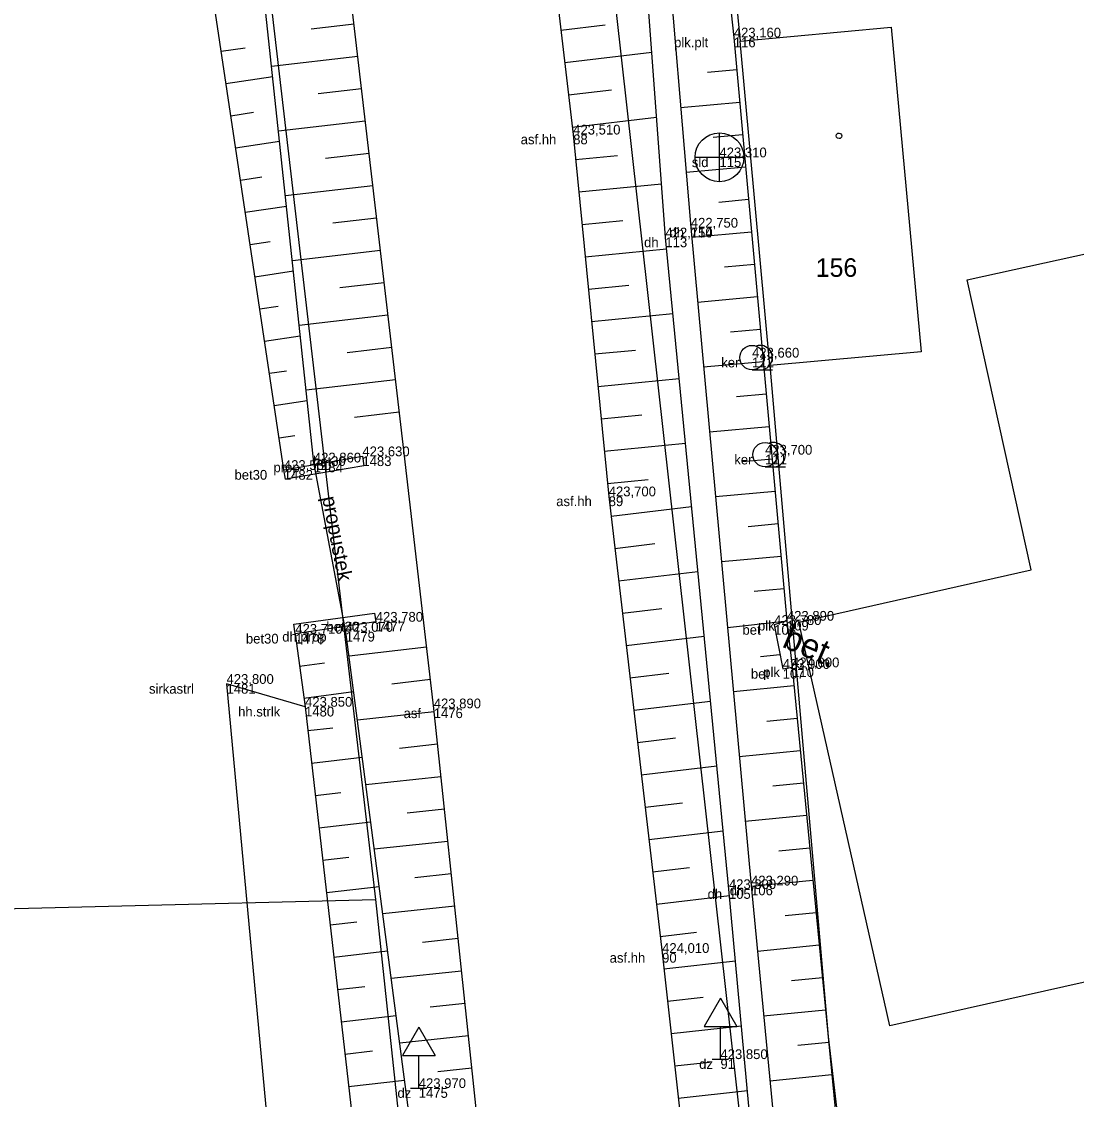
# Model space of a CAD drawing. Extents: x -747792 to -745414, y -1093712 to -1091463.
# Drawn here: x -746652 to -746619.62, y -1092747.87 to -1092714.77 of the extents above; entities that cross this region are included whole.
import ezdxf

# ---------------------------------------------------------------- set-up
doc = ezdxf.new("R2010")
doc.units = 0
for name, color, linetype in [('Hladina', 7, 'Continuous'), ('Koleje_dopravní prvky', 7, 'Continuous'), ('Nezařazené objekty', 7, 'Continuous'), ('Nivelační značky_hrany', 7, 'Continuous'), ('Názvy obcí_ulic', 7, 'Continuous'), ('Ploty_opěrné zdi', 7, 'Continuous'), ('Pracovní_bod JDTM STC_VC - výška', 7, 'Continuous'), ('Pracovní_bod PPBP', 7, 'Continuous'), ('Pracovní_bod PPBP - číslo', 7, 'Continuous'), ('Pracovní_bod ZPBP', 7, 'Continuous'), ('Pracovní_bod ZPBP - číslo', 7, 'Continuous'), ('Rozhraní ploch', 7, 'Continuous'), ('Stromy_porost', 7, 'Continuous'), ('Výškopis', 7, 'Continuous'), ('Čísla popisná_parcelní', 7, 'Continuous')]:
    doc.layers.add(name, color=color, linetype=linetype)

msp = doc.modelspace()

# ---------------------------------------------------------------- linework, layer by layer
at = {"layer": 'Hladina'}
for p, q in [((-746630.14, -1092715.26), (-746630.14, -1092715.26)), ((-746635.07, -1092718.24), (-746635.07, -1092718.24)), ((-746630.58, -1092718.94), (-746630.58, -1092718.94)), ((-746631.46, -1092721.1), (-746631.46, -1092721.1)), ((-746632.24, -1092721.4), (-746632.24, -1092721.4)), ((-746629.58, -1092725.09), (-746629.58, -1092725.09)), ((-746641.54, -1092728.12), (-746641.54, -1092728.12)), ((-746629.18, -1092728.07), (-746629.18, -1092728.07)), ((-746643.95, -1092728.54), (-746643.95, -1092728.54)), ((-746643.03, -1092728.31), (-746643.03, -1092728.31)), ((-746633.98, -1092729.35), (-746633.98, -1092729.35)), ((-746641.13, -1092733.2), (-746641.13, -1092733.2)), ((-746628.51, -1092733.17), (-746628.51, -1092733.17)), ((-746642.05, -1092733.51), (-746642.05, -1092733.51)), ((-746628.9, -1092733.3), (-746628.9, -1092733.3)), ((-746643.6, -1092733.57), (-746643.6, -1092733.57)), ((-746628.64, -1092734.65), (-746628.64, -1092734.65)), ((-746628.35, -1092734.6), (-746628.35, -1092734.6)), ((-746645.71, -1092735.11), (-746645.71, -1092735.11)), ((-746643.3, -1092735.81), (-746643.3, -1092735.81)), ((-746639.35, -1092735.86), (-746639.35, -1092735.86)), ((-746630.29, -1092741.41), (-746630.29, -1092741.41)), ((-746629.61, -1092741.3), (-746629.61, -1092741.3)), ((-746632.34, -1092743.37), (-746632.34, -1092743.37)), ((-746630.55, -1092746.63), (-746630.55, -1092746.63)), ((-746639.81, -1092747.52), (-746639.81, -1092747.52))]:
    msp.add_line(p, q, dxfattribs=at)
at = {"layer": 'Nezařazené objekty'}
for points in [[(-746631.05, -1092667.87), (-746635.97, -1092668.97), (-746634.11, -1092682.81), (-746632.69, -1092695.31), (-746631.46, -1092703.01), (-746630.14, -1092715.26)], [(-746630.14, -1092715.26), (-746628.51, -1092733.17), (-746628.35, -1092734.6), (-746626.39, -1092754.68)]]:
    msp.add_lwpolyline(points, dxfattribs=at)
at = {"layer": 'Nivelační značky_hrany'}
for points in [[(-746640.293, -1092727.76), (-746642.73, -1092706.84), (-746645.07, -1092684.23), (-746647.45, -1092662.17), (-746649.23, -1092645.87), (-746651.64, -1092623.4), (-746654, -1092600.5), (-746655.65, -1092585.38), (-746656.67, -1092576.42), (-746659.12, -1092561.65), (-746661.88, -1092550.86), (-746667.11, -1092535.97), (-746671.93, -1092526), (-746677.329, -1092516.06)], [(-746638.62, -1092670.38), (-746639.61, -1092674.4), (-746639.44, -1092678.91), (-746638.64, -1092688.08), (-746636.95, -1092702.22), (-746635.07, -1092718.24), (-746633.98, -1092729.35), (-746632.34, -1092743.37), (-746630.46, -1092760.33), (-746628.78, -1092773.02)], [(-746639.676, -1092733.059), (-746640.293, -1092727.763)], [(-746643.95, -1092728.54), (-746641.54, -1092728.12), (-746641.491, -1092728.416), (-746643.897, -1092728.82), (-746643.95, -1092728.54)], [(-746641.13, -1092733.2), (-746643.6, -1092733.57), (-746643.64, -1092733.273), (-746641.172, -1092732.94), (-746641.13, -1092733.2)], [(-746631.6, -1092801.51), (-746633.92, -1092784.4), (-746635.62, -1092771.08), (-746639.35, -1092735.86), (-746639.676, -1092733.06)], [(-746628.51, -1092733.17), (-746628.9, -1092733.3), (-746628.64, -1092734.65), (-746628.35, -1092734.6)]]:
    msp.add_lwpolyline(points, dxfattribs=at)
at = {"layer": 'Názvy obcí_ulic'}
for p, q in [((-746630.55, -1092744.764), (-746631.05, -1092745.63)), ((-746630.55, -1092744.764), (-746630.05, -1092745.63)), ((-746639.81, -1092745.654), (-746640.31, -1092746.52)), ((-746639.81, -1092745.654), (-746639.31, -1092746.52)), ((-746631.05, -1092745.63), (-746630.05, -1092745.63)), ((-746630.55, -1092746.63), (-746630.55, -1092745.63)), ((-746640.31, -1092746.52), (-746639.31, -1092746.52)), ((-746639.81, -1092747.52), (-746639.81, -1092746.52)), ((-746630.8, -1092746.63), (-746630.3, -1092746.63)), ((-746640.06, -1092747.52), (-746639.56, -1092747.52))]:
    msp.add_line(p, q, dxfattribs=at)
at = {"layer": 'Ploty_opěrné zdi'}
msp.add_lwpolyline([(-746626.91, -1092718.195), (-746626.86, -1092718.205), (-746626.835, -1092718.25), (-746626.825, -1092718.28), (-746626.835, -1092718.325), (-746626.875, -1092718.36), (-746626.91, -1092718.365), (-746626.955, -1092718.35), (-746626.985, -1092718.32), (-746626.995, -1092718.28), (-746626.985, -1092718.235), (-746626.945, -1092718.2)], close=True, dxfattribs=at)
at = {"layer": 'Pracovní_bod JDTM STC_VC - výška'}
msp.add_lwpolyline([(-746643.3, -1092735.81), (-746645.71, -1092735.11), (-746642.51, -1092769.58), (-746639.22, -1092771.37)], dxfattribs=at)
at = {"layer": 'Pracovní_bod PPBP'}
for points in [[(-746643.03, -1092728.31), (-746645.35, -1092706.55), (-746647.64, -1092685.53), (-746650.22, -1092662.21), (-746652.01, -1092645.97), (-746654.41, -1092623.21), (-746657.16, -1092600.72), (-746657.52, -1092586.28), (-746659.03, -1092575.98), (-746661.36, -1092561.58), (-746663.99, -1092551.17), (-746668.72, -1092536.82), (-746673.6, -1092526.76), (-746679.03, -1092516.89)], [(-746643.95, -1092728.54), (-746647.21, -1092706.78), (-746649.33, -1092686.28), (-746651.4, -1092662.02)], [(-746627.38, -1092772.91), (-746628.52, -1092760.62), (-746630.29, -1092741.41), (-746632.24, -1092721.4), (-746632.95, -1092711.71), (-746633.31, -1092703.22), (-746634.38, -1092695.54), (-746635.8, -1092684.01), (-746637.93, -1092670.61)], [(-746637.24, -1092670.41), (-746635.08, -1092683.82), (-746633.69, -1092695.33), (-746632.62, -1092703.25), (-746632.27, -1092711.5), (-746631.46, -1092721.1), (-746629.61, -1092741.3), (-746627.76, -1092760.57), (-746626.45, -1092772.93)], [(-746641.797, -1092714.848), (-746643.115, -1092715.001)], [(-746635.446, -1092715.033), (-746634.088, -1092714.874)], [(-746645.876, -1092715.683), (-746645.138, -1092715.573)], [(-746641.682, -1092715.841), (-746644.327, -1092716.149)], [(-746635.33, -1092716.026), (-746632.657, -1092715.713)], [(-746630.049, -1092716.256), (-746630.952, -1092716.338)], [(-746645.728, -1092716.672), (-746644.294, -1092716.458)], [(-746641.566, -1092716.834), (-746642.893, -1092716.989)], [(-746635.213, -1092717.02), (-746633.898, -1092716.865)], [(-746629.959, -1092717.252), (-746631.771, -1092717.417)], [(-746645.58, -1092717.661), (-746644.884, -1092717.557)], [(-746641.45, -1092717.828), (-746644.115, -1092718.138)], [(-746635.097, -1092718.013), (-746632.51, -1092717.709)], [(-746629.868, -1092718.248), (-746630.777, -1092718.33)], [(-746645.432, -1092718.65), (-746644.081, -1092718.448)], [(-746641.335, -1092718.821), (-746642.672, -1092718.977)], [(-746634.995, -1092719.008), (-746633.714, -1092718.882)], [(-746629.777, -1092719.244), (-746631.603, -1092719.41)], [(-746645.283, -1092719.639), (-746644.629, -1092719.541)], [(-746641.219, -1092719.814), (-746643.902, -1092720.127)], [(-746634.897, -1092720.003), (-746632.361, -1092719.754)], [(-746629.687, -1092720.239), (-746630.603, -1092720.323)], [(-746645.135, -1092720.628), (-746643.869, -1092720.439)], [(-746641.103, -1092720.807), (-746642.45, -1092720.964)], [(-746634.799, -1092720.998), (-746633.543, -1092720.875)], [(-746629.596, -1092721.235), (-746631.432, -1092721.402)], [(-746644.987, -1092721.617), (-746644.375, -1092721.526)], [(-746640.988, -1092721.801), (-746643.69, -1092722.115)], [(-746634.702, -1092721.993), (-746632.206, -1092721.748)], [(-746629.506, -1092722.231), (-746630.423, -1092722.315)], [(-746644.839, -1092722.606), (-746643.657, -1092722.429)], [(-746640.872, -1092722.794), (-746642.228, -1092722.952)], [(-746634.604, -1092722.988), (-746633.357, -1092722.866)], [(-746629.415, -1092723.227), (-746631.25, -1092723.394)], [(-746644.691, -1092723.595), (-746644.121, -1092723.51)], [(-746640.756, -1092723.787), (-746643.478, -1092724.104)], [(-746634.506, -1092723.984), (-746632.012, -1092723.739)], [(-746629.324, -1092724.223), (-746630.241, -1092724.306)], [(-746644.543, -1092724.584), (-746643.445, -1092724.42)], [(-746640.64, -1092724.781), (-746642.006, -1092724.94)], [(-746634.409, -1092724.979), (-746633.162, -1092724.857)], [(-746629.234, -1092725.219), (-746631.067, -1092725.386)], [(-746644.394, -1092725.573), (-746643.867, -1092725.494)], [(-746640.525, -1092725.774), (-746643.266, -1092726.093)], [(-746634.311, -1092725.974), (-746631.818, -1092725.73)], [(-746629.143, -1092726.215), (-746630.06, -1092726.298)], [(-746644.246, -1092726.562), (-746643.233, -1092726.41)], [(-746640.409, -1092726.767), (-746641.785, -1092726.927)], [(-746634.214, -1092726.969), (-746632.967, -1092726.847)], [(-746629.052, -1092727.211), (-746630.885, -1092727.377)], [(-746644.098, -1092727.551), (-746643.612, -1092727.478)], [(-746634.116, -1092727.965), (-746631.624, -1092727.72)], [(-746628.962, -1092728.206), (-746629.878, -1092728.29)], [(-746634.018, -1092728.96), (-746632.773, -1092728.838)], [(-746628.871, -1092729.202), (-746630.703, -1092729.369)], [(-746633.909, -1092729.954), (-746631.435, -1092729.664)], [(-746628.78, -1092730.198), (-746629.696, -1092730.282)], [(-746633.793, -1092730.947), (-746632.565, -1092730.803)], [(-746628.69, -1092731.194), (-746630.52, -1092731.361)], [(-746633.677, -1092731.94), (-746631.241, -1092731.655)], [(-746628.599, -1092732.19), (-746629.514, -1092732.273)], [(-746633.561, -1092732.934), (-746632.352, -1092732.792)], [(-746628.595, -1092733.196), (-746630.334, -1092733.39)], [(-746633.23, -1092801.81), (-746633.34, -1092799.18), (-746635.14, -1092785.2), (-746636.97, -1092772.24), (-746642.05, -1092733.51)], [(-746643.6, -1092733.57), (-746643.3, -1092735.81), (-746639.22, -1092771.37), (-746638.71, -1092772.84), (-746637.46, -1092782.53), (-746636.71, -1092786.88), (-746634.79, -1092797.88), (-746635.62, -1092802.2)], [(-746633.445, -1092733.927), (-746631.047, -1092733.646)], [(-746639.568, -1092733.984), (-746641.951, -1092734.262)], [(-746643.467, -1092734.561), (-746642.703, -1092734.459)], [(-746628.723, -1092734.216), (-746629.32, -1092734.283)], [(-746633.328, -1092734.92), (-746632.139, -1092734.781)], [(-746639.453, -1092734.978), (-746640.637, -1092735.115)], [(-746628.294, -1092735.174), (-746630.154, -1092735.356)], [(-746643.335, -1092735.552), (-746641.809, -1092735.348)], [(-746633.212, -1092735.913), (-746630.853, -1092735.637)], [(-746639.338, -1092735.971), (-746641.694, -1092736.22)], [(-746628.197, -1092736.17), (-746629.13, -1092736.261)], [(-746643.216, -1092736.545), (-746642.445, -1092736.457)], [(-746633.096, -1092736.906), (-746631.926, -1092736.77)], [(-746639.233, -1092736.965), (-746640.399, -1092737.089)], [(-746628.1, -1092737.165), (-746629.972, -1092737.348)], [(-746643.102, -1092737.539), (-746641.545, -1092737.36)], [(-746632.98, -1092737.9), (-746630.659, -1092737.628)], [(-746639.128, -1092737.96), (-746641.434, -1092738.204)], [(-746628.002, -1092738.16), (-746628.942, -1092738.252)], [(-746642.988, -1092738.532), (-746642.201, -1092738.442)], [(-746632.864, -1092738.893), (-746631.713, -1092738.758)], [(-746639.022, -1092738.954), (-746640.163, -1092739.075)], [(-746627.905, -1092739.155), (-746629.79, -1092739.339)], [(-746642.874, -1092739.526), (-746641.285, -1092739.343)], [(-746632.748, -1092739.886), (-746630.465, -1092739.619)], [(-746638.917, -1092739.949), (-746641.174, -1092740.188)], [(-746627.808, -1092740.151), (-746628.753, -1092740.243)], [(-746642.76, -1092740.519), (-746641.957, -1092740.427)], [(-746632.631, -1092740.879), (-746631.499, -1092740.747)], [(-746638.812, -1092740.943), (-746639.928, -1092741.061)], [(-746627.711, -1092741.146), (-746629.607, -1092741.331)], [(-746642.646, -1092741.513), (-746641.025, -1092741.327)], [(-746632.515, -1092741.873), (-746630.272, -1092741.61)], [(-746638.706, -1092741.938), (-746640.914, -1092742.171)], [(-746627.614, -1092742.141), (-746628.563, -1092742.234)], [(-746642.532, -1092742.506), (-746641.713, -1092742.412)], [(-746632.399, -1092742.866), (-746631.289, -1092742.736)], [(-746638.601, -1092742.932), (-746639.692, -1092743.048)], [(-746627.517, -1092743.136), (-746629.416, -1092743.322)], [(-746642.418, -1092743.5), (-746640.765, -1092743.31)], [(-746632.286, -1092743.859), (-746630.087, -1092743.616)], [(-746638.496, -1092743.926), (-746640.654, -1092744.155)], [(-746627.42, -1092744.132), (-746628.37, -1092744.225)], [(-746642.304, -1092744.493), (-746641.469, -1092744.397)], [(-746632.176, -1092744.853), (-746631.085, -1092744.732)], [(-746638.39, -1092744.921), (-746639.457, -1092745.034)], [(-746627.322, -1092745.127), (-746629.225, -1092745.313)], [(-746642.19, -1092745.487), (-746640.504, -1092745.293)], [(-746632.065, -1092745.847), (-746629.903, -1092745.608)], [(-746638.285, -1092745.915), (-746640.394, -1092746.139)], [(-746642.076, -1092746.48), (-746641.225, -1092746.382)], [(-746627.225, -1092746.122), (-746628.177, -1092746.215)], [(-746631.955, -1092746.841), (-746630.883, -1092746.722)], [(-746638.18, -1092746.91), (-746639.222, -1092747.02)], [(-746641.962, -1092747.473), (-746640.244, -1092747.276)], [(-746627.128, -1092747.118), (-746629.034, -1092747.304)], [(-746631.845, -1092747.835), (-746629.72, -1092747.599)]]:
    msp.add_lwpolyline(points, dxfattribs=at)
at = {"layer": 'Pracovní_bod PPBP - číslo'}
for p, q in [((-746629.58, -1092725.465), (-746628.955, -1092725.465)), ((-746629.18, -1092728.445), (-746628.555, -1092728.445))]:
    msp.add_line(p, q, dxfattribs=at)
for centre in [(-746629.58, -1092725.09), (-746629.18, -1092728.07)]:
    msp.add_circle(centre, 0.375, dxfattribs=at)
for centre in [(-746629.33, -1092725.09), (-746628.93, -1092728.07)]:
    msp.add_arc(centre, 0.375, 249.4944, 109.0474, dxfattribs=at)
at = {"layer": 'Pracovní_bod ZPBP'}
msp.add_lwpolyline([(-746642.05, -1092733.51), (-746643.03, -1092728.31)], dxfattribs=at)
at = {"layer": 'Stromy_porost'}
for points in [[(-746635.22, -1092661.8), (-746629.94, -1092715.37)], [(-746635.99, -1092694.45), (-746628.46, -1092761.78)], [(-746645.62, -1092703.3), (-746641.14, -1092741.73)], [(-746629.94, -1092715.37), (-746625.31, -1092714.94)], [(-746625.31, -1092714.94), (-746624.39, -1092724.91)], [(-746629.03, -1092725.33), (-746629.94, -1092715.37)], [(-746622.98, -1092722.7), (-746607.9, -1092719.39)], [(-746621.01, -1092731.61), (-746622.98, -1092722.7)], [(-746624.39, -1092724.91), (-746629.03, -1092725.33)], [(-746629.03, -1092725.33), (-746627.24, -1092745.94)], [(-746628.14, -1092733.21), (-746621.01, -1092731.61)], [(-746625.35, -1092745.61), (-746628.14, -1092733.21)], [(-746682.12, -1092742.75), (-746641.14, -1092741.73)], [(-746641.14, -1092741.73), (-746637.96, -1092771.64)], [(-746610.42, -1092742.26), (-746625.35, -1092745.61)], [(-746627.24, -1092745.94), (-746621.8, -1092792.34)]]:
    msp.add_lwpolyline(points, dxfattribs=at)
at = {"layer": 'Čísla popisná_parcelní'}
for p, q in [((-746630.581, -1092719.688), (-746630.58, -1092718.193)), ((-746629.828, -1092718.946), (-746631.328, -1092718.941))]:
    msp.add_line(p, q, dxfattribs=at)
msp.add_circle((-746630.58, -1092718.94), 0.75, dxfattribs=at)

# ---------------------------------------------------------------- texts
at = {"layer": 'Koleje_dopravní prvky'}
msp.add_text('156', height=0.57, dxfattribs=at).set_placement((-746627.624, -1092722.61))
at = {"layer": 'Pracovní_bod ZPBP - číslo'}
for s, height, rotation, p in [('propustek', 0.45, 280.8807, (-746642.779, -1092729.387)), ('bet.', 0.75, 336.8014, (-746628.691, -1092733.96))]:
    msp.add_text(s, height=height, rotation=rotation, dxfattribs=at).set_placement(p)
at = {"layer": 'Rozhraní ploch'}
for s, p in [(' plk.plt', (-746632.084, -1092715.56)), ('116', (-746630.14, -1092715.56)), (' asf.hh', (-746636.792, -1092718.54)), ('88', (-746635.07, -1092718.54)), (' sld', (-746631.541, -1092719.24)), ('115', (-746630.58, -1092719.24)), (' dh', (-746632.225, -1092721.4)), ('114', (-746631.46, -1092721.4)), (' dh', (-746633.005, -1092721.7)), ('113', (-746632.24, -1092721.7)), (' ker', (-746630.636, -1092725.39)), ('112', (-746629.58, -1092725.39)), (' bet30', (-746643.167, -1092728.42)), ('1483', (-746641.54, -1092728.42)), (' ker', (-746630.236, -1092728.37)), ('111', (-746629.18, -1092728.37)), (' bet30', (-746645.577, -1092728.84)), (' prop', (-746644.381, -1092728.61)), ('1482', (-746643.95, -1092728.84)), ('1484', (-746643.03, -1092728.61)), (' asf.hh', (-746635.702, -1092729.65)), ('89', (-746633.98, -1092729.65)), (' bet30', (-746642.757, -1092733.5)), ('1477', (-746641.13, -1092733.5)), (' plk', (-746629.509, -1092733.47)), ('109', (-746628.51, -1092733.47)), (' dh.prop', (-746644.112, -1092733.81)), ('1479', (-746642.05, -1092733.81)), (' bet', (-746629.986, -1092733.6)), ('108', (-746628.9, -1092733.6)), (' bet30', (-746645.227, -1092733.87)), ('1478', (-746643.6, -1092733.87)), (' bet', (-746629.726, -1092734.95)), (' plk', (-746629.349, -1092734.9)), ('107', (-746628.64, -1092734.95)), ('110', (-746628.35, -1092734.9)), (' sirkastrl', (-746648.202, -1092735.41)), ('1481', (-746645.71, -1092735.41)), (' hh.strlk', (-746645.466, -1092736.11)), ('1480', (-746643.3, -1092736.11)), (' asf', (-746640.387, -1092736.16)), ('1476', (-746639.35, -1092736.16)), (' dh', (-746631.055, -1092741.71)), ('105', (-746630.29, -1092741.71)), (' dh', (-746630.375, -1092741.6)), ('106', (-746629.61, -1092741.6)), (' asf.hh', (-746634.062, -1092743.67)), ('90', (-746632.34, -1092743.67)), (' dz', (-746631.315, -1092746.93)), ('91', (-746630.55, -1092746.93)), (' dz', (-746640.575, -1092747.82)), ('1475', (-746639.81, -1092747.82))]:
    msp.add_text(s, height=0.3, dxfattribs=at).set_placement(p)
at = {"layer": 'Výškopis'}
for s, p in [('423,160', (-746630.14, -1092715.26)), ('423,510', (-746635.07, -1092718.24)), ('423,310', (-746630.58, -1092718.94)), ('422,750', (-746631.46, -1092721.1)), ('422,750', (-746632.24, -1092721.4)), ('423,660', (-746629.58, -1092725.09)), ('423,630', (-746641.54, -1092728.12)), ('423,700', (-746629.18, -1092728.07)), ('423,530', (-746643.95, -1092728.54)), ('422,860', (-746643.03, -1092728.31)), ('423,700', (-746633.98, -1092729.35)), ('423,890', (-746628.51, -1092733.17)), ('423,070', (-746642.05, -1092733.51)), ('423,780', (-746641.13, -1092733.2)), ('423,780', (-746628.9, -1092733.3)), ('423,710', (-746643.6, -1092733.57)), ('423,900', (-746628.64, -1092734.65)), ('424,000', (-746628.35, -1092734.6)), ('423,800', (-746645.71, -1092735.11)), ('423,850', (-746643.3, -1092735.81)), ('423,890', (-746639.35, -1092735.86)), ('423,300', (-746630.29, -1092741.41)), ('423,290', (-746629.61, -1092741.3)), ('424,010', (-746632.34, -1092743.37)), ('423,850', (-746630.55, -1092746.63)), ('423,970', (-746639.81, -1092747.52))]:
    msp.add_text(s, height=0.3, dxfattribs=at).set_placement(p)

doc.saveas('drawing.dxf')
